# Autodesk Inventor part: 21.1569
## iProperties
Created: 2012-02
Part Number: 21.1569
Document SubType Name: Modeling
Designer: Administrator
Density: 7.85 g/cm^3
Material: Steel
Mass: 4.86141 g
Surface Area: 8.61152 cm^2
Volume: 0.619288 cm^3
Description: M6 SQUARE NUT 30
Vendor: S
Author: Administrator
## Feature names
1. Extrusion1
2. Extrusion2
3. Fillet1
4. Hole1
5. Extrusion3
6. Extrusion4
7. Fillet2
